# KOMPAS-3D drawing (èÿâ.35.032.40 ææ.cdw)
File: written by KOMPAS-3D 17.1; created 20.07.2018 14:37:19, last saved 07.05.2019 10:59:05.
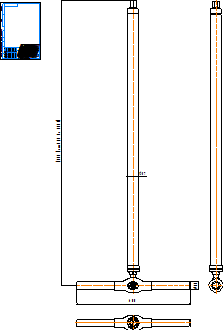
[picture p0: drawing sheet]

Sheet 1: A4, portrait

Title block, sheet 1: name: КШГ.35.032.40 СС; material: Внимание! Данный продукт является объектом авторского права ООО «Торговый Дом АДЛ». / Запрещается изменение, копирование, распространение / (в том числе путем копирования на другие сайты и ресурсы в Интернете) / или любое иное использование информации и объектов без предварительного / согласия правообладателя (ООО «Торговый Дом АДЛ»).; sheets: 1; organisation: ООО "Торговый дом АДЛ"; sheet format: A4; stored path: C:\Users\tra\Desktop\2д чертежи\Шаровые краны БИВАЛ\КШ_Бивал_серия_34_35\KOMPAS 2D\КШГ.35.032.40 СС.cdw

Views: Вид 1, Проекционный вид 2, Проекционный вид 3
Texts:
  kka
  adl
  (от 245 до 5000)
Dimensions and other numbers on the sheet: 600; 1500; 38; 57; 1:1; 1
